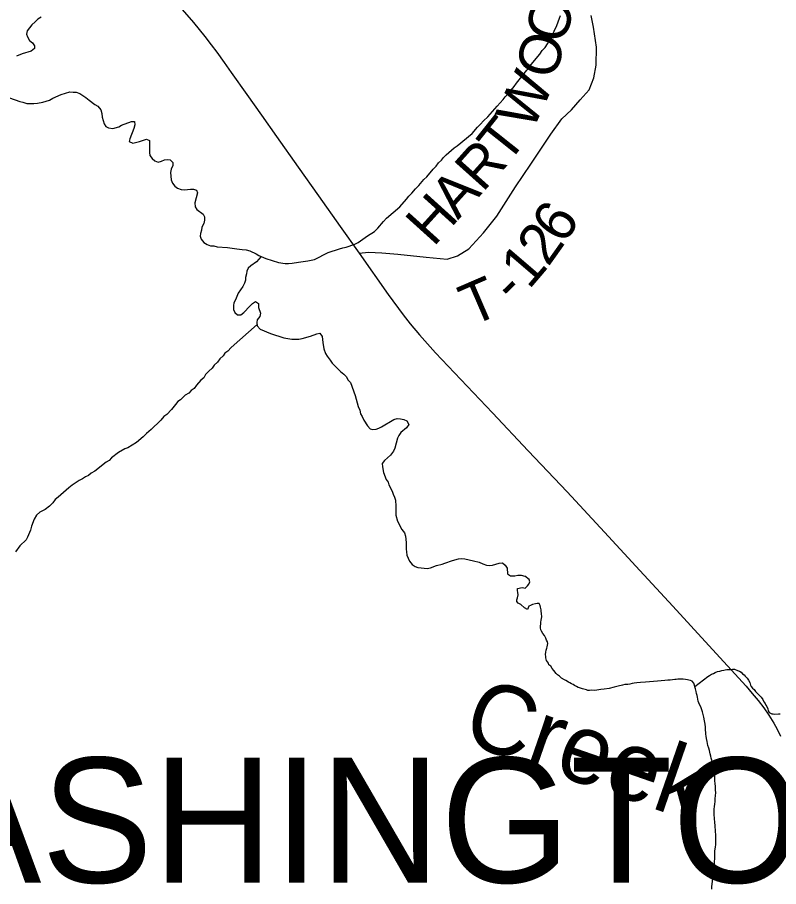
# Model space of a CAD drawing. Extents: x -14196 to 143, y -6096 to 28.
# Drawn here: x 62.594 to 63.633, y 20.504 to 21.69 of the extents above; entities that cross this region are included whole.
import ezdxf

# ---------------------------------------------------------------- set-up
doc = ezdxf.new("R2010")
doc.units = 0
for name, color, linetype in [('GM_X_Minor_River', 7, 'Continuous'), ('GM_X_Minor_River_Text', 7, 'Continuous'), ('GM_X_State_Route', 7, 'Continuous'), ('GM_X_Township_Road', 7, 'Continuous'), ('GM_X_Township_Road_Text', 7, 'Continuous'), ('GM_X_Township_Text', 7, 'Continuous')]:
    doc.layers.add(name, color=color, linetype=linetype)

msp = doc.modelspace()

# ---------------------------------------------------------------- linework, layer by layer
at = {"layer": 'GM_X_Minor_River'}
for points in [[(62.6266, 21.6899), (62.622, 21.6872), (62.6182, 21.6834), (62.6137, 21.6795), (62.6073, 21.6711), (62.6066, 21.6666)], [(62.9008, 21.373), (62.9062, 21.3723), (62.9111, 21.3712), (62.9196, 21.3671), (62.9234, 21.3648), (62.9329, 21.3608), (62.9501, 21.3552), (62.9593, 21.3538), (62.9639, 21.3538), (62.9688, 21.3543), (62.9775, 21.3559), (62.9905, 21.3575), (62.995, 21.3583), (62.9992, 21.3595), (63.0181, 21.3688), (63.0337, 21.3739), (63.0379, 21.3751), (63.0424, 21.3763), (63.0546, 21.3802), (63.0591, 21.3825), (63.0716, 21.3914), (63.0814, 21.3975), (63.0859, 21.4021), (63.0934, 21.4113), (63.0976, 21.4155), (63.1157, 21.4313), (63.1251, 21.4417), (63.1281, 21.4459), (63.1322, 21.4497), (63.1371, 21.4555), (63.142, 21.4604), (63.1488, 21.4685), (63.1529, 21.4723), (63.1612, 21.4827), (63.1654, 21.4865), (63.1687, 21.4911), (63.1725, 21.4946), (63.1755, 21.4984), (63.1793, 21.5022), (63.1898, 21.5118), (63.194, 21.5145), (63.2144, 21.5314), (63.2219, 21.5399), (63.226, 21.5437), (63.2302, 21.5483), (63.2358, 21.5537), (63.2486, 21.5686), (63.2569, 21.5775), (63.2595, 21.5813), (63.2637, 21.5855), (63.272, 21.5955), (63.275, 21.6), (63.2892, 21.6177), (63.2926, 21.6215), (63.2952, 21.6253), (63.3069, 21.6395), (63.3103, 21.6445), (63.314, 21.6483), (63.3174, 21.6533), (63.3226, 21.6632), (63.3301, 21.6785), (63.3338, 21.6884), (63.3349, 21.6922)], [(62.6066, 21.6666), (62.6078, 21.6628), (62.6105, 21.6582), (62.6144, 21.6548), (62.6171, 21.6507), (62.6171, 21.6469), (62.6129, 21.6434), (62.6004, 21.6399), (62.5928, 21.6368)], [(62.5832, 21.5797), (62.5973, 21.5749), (62.6015, 21.5738), (62.6068, 21.5723), (62.6164, 21.572), (62.6213, 21.5724), (62.6289, 21.574), (62.638, 21.5768), (62.6422, 21.5795), (62.6535, 21.5845), (62.6657, 21.5881), (62.6699, 21.5877), (62.674, 21.5874), (62.679, 21.5859), (62.6874, 21.5803), (62.6917, 21.5765), (62.6997, 21.5705), (62.7036, 21.5683), (62.7078, 21.5634), (62.7094, 21.5585), (62.7098, 21.5535), (62.7122, 21.5444), (62.7145, 21.5407), (62.7183, 21.5388), (62.724, 21.5381), (62.7324, 21.5401), (62.7362, 21.5424), (62.7498, 21.5475), (62.7536, 21.5475), (62.7544, 21.543), (62.753, 21.538), (62.7474, 21.5239), (62.7467, 21.5201), (62.7517, 21.5178), (62.7608, 21.5202), (62.7703, 21.5233), (62.7741, 21.5215), (62.7742, 21.5051), (62.7747, 21.501), (62.7778, 21.4972), (62.7816, 21.4938), (62.7862, 21.4923), (62.7907, 21.4935), (62.7945, 21.4951), (62.7987, 21.4955), (62.8025, 21.4952), (62.806, 21.4914), (62.806, 21.4876), (62.8038, 21.4826), (62.8027, 21.4781), (62.8036, 21.4682), (62.8055, 21.4633), (62.8086, 21.4595), (62.8124, 21.4565), (62.8174, 21.455), (62.822, 21.4543), (62.8303, 21.4551), (62.8345, 21.4552), (62.8383, 21.4541), (62.8399, 21.4503), (62.8359, 21.4366), (62.8367, 21.4313), (62.839, 21.4275), (62.8474, 21.4211), (62.8494, 21.4173), (62.8494, 21.4132), (62.8483, 21.4082), (62.8457, 21.4036), (62.845, 21.3994), (62.8439, 21.3949), (62.8436, 21.3911), (62.8447, 21.3869), (62.8486, 21.3827), (62.8528, 21.3797), (62.8574, 21.3779), (62.862, 21.3779), (62.8665, 21.3768), (62.8806, 21.3758), (62.8932, 21.3737), (62.897, 21.3733), (62.9008, 21.373)], [(62.9268, 21.3634), (62.9204, 21.3561), (62.9125, 21.3507), (62.9087, 21.3476), (62.9069, 21.3434), (62.9065, 21.3396), (62.9054, 21.335), (62.9051, 21.3312), (62.904, 21.327), (62.9014, 21.3225), (62.8954, 21.3133), (62.8917, 21.3041), (62.8894, 21.3003), (62.8887, 21.2965), (62.8891, 21.2912), (62.8907, 21.287), (62.8945, 21.284), (62.8991, 21.284), (62.9029, 21.2871), (62.9112, 21.2959), (62.9149, 21.2994), (62.9191, 21.3021), (62.9229, 21.2991), (62.923, 21.2938), (62.9257, 21.2862), (62.9246, 21.2816), (62.9213, 21.277), (62.9205, 21.2732), (62.9213, 21.2687), (62.9252, 21.2642), (62.9393, 21.2586), (62.9577, 21.2523), (62.9683, 21.2505), (62.9725, 21.2506), (62.9782, 21.2506), (62.9828, 21.2514), (62.9938, 21.2546), (63.0025, 21.2581), (63.0067, 21.2589), (63.0098, 21.2543), (63.0106, 21.246), (63.0123, 21.2373), (63.0146, 21.2312), (63.0169, 21.2274), (63.0208, 21.2221), (63.0235, 21.218), (63.035, 21.2067), (63.0396, 21.2029), (63.0431, 21.1992), (63.045, 21.1954), (63.0485, 21.1916), (63.0548, 21.1738), (63.0591, 21.1587), (63.0611, 21.1538), (63.0623, 21.1488), (63.0646, 21.145), (63.0666, 21.1401), (63.0716, 21.1326), (63.0754, 21.1284), (63.0792, 21.1273), (63.0834, 21.1281), (63.0872, 21.1293), (63.091, 21.1312), (63.1076, 21.1413), (63.1122, 21.1425), (63.1168, 21.1421), (63.1214, 21.141), (63.1252, 21.1392), (63.1283, 21.1343), (63.1249, 21.1297), (63.117, 21.1235), (63.1143, 21.1193), (63.1125, 21.1155), (63.1092, 21.1022), (63.1073, 21.098), (63.1032, 21.0926), (63.0991, 21.0888), (63.0949, 21.0853), (63.0919, 21.0811), (63.092, 21.0765), (63.0936, 21.0689), (63.0971, 21.0595), (63.0998, 21.0557), (63.101, 21.0519), (63.1056, 21.0432), (63.1068, 21.0394), (63.1087, 21.0353), (63.1099, 21.0311), (63.1104, 21.0227), (63.1105, 21.0106), (63.1125, 21.0026), (63.1187, 20.9909), (63.1222, 20.9864), (63.1238, 20.9822), (63.1246, 20.9735), (63.1243, 20.9689), (63.1247, 20.9644), (63.1251, 20.9606), (63.1252, 20.956), (63.1291, 20.9477), (63.1325, 20.9432)], [(62.921, 21.2705), (62.8855, 21.2391), (62.8813, 21.2345), (62.8772, 21.2318), (62.8749, 21.228), (62.8704, 21.2237), (62.867, 21.2191), (62.8625, 21.2153), (62.8599, 21.2111), (62.8554, 21.2072), (62.8508, 21.2023), (62.8482, 21.1981), (62.8445, 21.1946), (62.8384, 21.1881), (62.8354, 21.1835), (62.8309, 21.1808), (62.8279, 21.177), (62.823, 21.1743), (62.8166, 21.1681), (62.8128, 21.1658), (62.8098, 21.1616), (62.8041, 21.1547), (62.7977, 21.1478), (62.794, 21.1451), (62.7898, 21.1401), (62.7853, 21.1355), (62.7804, 21.1317), (62.7766, 21.1274), (62.7702, 21.1221), (62.7657, 21.1175), (62.7563, 21.1098), (62.7449, 21.1024), (62.7404, 21.1009), (62.732, 21.0962), (62.7222, 21.0889), (62.7192, 21.0851), (62.7151, 21.0828), (62.6996, 21.0705), (62.6947, 21.0678), (62.6909, 21.0647), (62.6867, 21.0631), (62.6829, 21.0604), (62.6784, 21.0581), (62.6686, 21.0515), (62.664, 21.0481), (62.6497, 21.035), (62.6455, 21.0319), (62.6422, 21.0273), (62.6376, 21.0231), (62.632, 21.0185), (62.6282, 21.0166), (62.6244, 21.0146), (62.6199, 21.0108), (62.6169, 21.0051), (62.6132, 20.9955), (62.6117, 20.9902), (62.608, 20.9807), (62.6058, 20.9768), (62.5975, 20.9688), (62.5915, 20.9604)], [(63.1325, 20.9432), (63.1367, 20.9405), (63.1406, 20.9394), (63.1448, 20.9387), (63.1531, 20.938), (63.1577, 20.9388), (63.166, 20.942), (63.1736, 20.9439), (63.1774, 20.9451), (63.1877, 20.9486), (63.196, 20.951), (63.2002, 20.9514), (63.2044, 20.9511), (63.2166, 20.9482), (63.2242, 20.9467), (63.2292, 20.9441), (63.2342, 20.9426), (63.2384, 20.9419), (63.2422, 20.9423), (63.2513, 20.9451), (63.2558, 20.9455), (63.2597, 20.9425), (63.2624, 20.9383), (63.2628, 20.9307), (63.2667, 20.928), (63.2726, 20.9277), (63.2768, 20.9287), (63.2815, 20.9287), (63.2864, 20.9276)], [(63.3725, 20.7717), (63.3706, 20.7725), (63.3652, 20.7739), (63.361, 20.775), (63.3591, 20.7758), (63.3568, 20.7769), (63.3542, 20.7784), (63.3522, 20.7795), (63.3499, 20.7806), (63.348, 20.7821), (63.3461, 20.7828), (63.3423, 20.7851), (63.3404, 20.7862), (63.3366, 20.7881), (63.3339, 20.7911), (63.3312, 20.7929), (63.3293, 20.7948), (63.3258, 20.7986), (63.3239, 20.8016), (63.3219, 20.8046), (63.3193, 20.8065), (63.3185, 20.8088), (63.3161, 20.8125), (63.3153, 20.816), (63.3149, 20.8179), (63.3145, 20.8205), (63.3149, 20.8239), (63.3156, 20.8266), (63.3163, 20.8293), (63.3171, 20.8312), (63.3174, 20.8335), (63.3178, 20.8354), (63.3174, 20.838), (63.3162, 20.8403), (63.315, 20.8429), (63.3131, 20.8463), (63.3111, 20.8494), (63.3092, 20.8524), (63.3084, 20.8543), (63.3076, 20.8569), (63.308, 20.8592), (63.3083, 20.8626), (63.3083, 20.8645), (63.3087, 20.8676), (63.309, 20.8695), (63.3097, 20.8718), (63.3093, 20.8767), (63.3089, 20.8797), (63.3085, 20.8816), (63.3077, 20.885), (63.3073, 20.8873), (63.3061, 20.89), (63.3034, 20.8903), (63.3008, 20.8899), (63.297, 20.8887), (63.294, 20.8876), (63.2921, 20.8864), (63.291, 20.8841), (63.2899, 20.8822), (63.286, 20.8844), (63.2811, 20.8886), (63.2772, 20.8908), (63.2757, 20.8931), (63.2757, 20.8953), (63.2764, 20.898), (63.2771, 20.9018), (63.2767, 20.9052), (63.2763, 20.9079), (63.2762, 20.9106), (63.2827, 20.9118), (63.285, 20.9114), (63.2869, 20.911), (63.2899, 20.9141), (63.2921, 20.9164), (63.2932, 20.9199), (63.2924, 20.9229), (63.2864, 20.9276)], [(63.5185, 20.7771), (63.536, 20.7906), (63.5382, 20.7921), (63.5412, 20.7937), (63.5439, 20.7948), (63.5461, 20.796), (63.5495, 20.7972), (63.5526, 20.798), (63.5552, 20.7988), (63.5579, 20.7992), (63.5598, 20.7996), (63.562, 20.8), (63.5647, 20.8), (63.567, 20.8), (63.57, 20.8004), (63.5723, 20.8005), (63.5765, 20.799), (63.5795, 20.7979), (63.5815, 20.7964), (63.5834, 20.7941), (63.5857, 20.793), (63.5872, 20.7911), (63.5899, 20.7881), (63.5918, 20.7855), (63.5934, 20.7824), (63.5942, 20.779), (63.5954, 20.7768), (63.5969, 20.7749), (63.5992, 20.773), (63.6011, 20.77), (63.6031, 20.7685), (63.6058, 20.7655), (63.6088, 20.7625), (63.6112, 20.7594), (63.6127, 20.756), (63.6143, 20.7538), (63.6154, 20.7515), (63.6166, 20.7496), (63.6178, 20.7466), (63.6186, 20.7439), (63.6197, 20.7417), (63.6216, 20.7406), (63.6235, 20.7398), (63.6254, 20.7395), (63.6273, 20.7391), (63.6327, 20.7395), (63.6349, 20.7396)], [(63.5469, 20.5722), (63.5469, 20.5752), (63.5468, 20.5786), (63.546, 20.5877), (63.5459, 20.5911), (63.5455, 20.593), (63.5451, 20.5957), (63.5451, 20.5984), (63.545, 20.601), (63.545, 20.6041), (63.545, 20.6071), (63.5449, 20.6098), (63.5453, 20.6132), (63.5456, 20.6166), (63.546, 20.62), (63.5463, 20.6238), (63.5466, 20.6284), (63.547, 20.6318), (63.5465, 20.636), (63.5465, 20.6406), (63.546, 20.6447), (63.5456, 20.6485), (63.5456, 20.6527), (63.5455, 20.6558), (63.5451, 20.658), (63.5447, 20.6611), (63.5443, 20.6637), (63.5435, 20.6664), (63.5431, 20.6694), (63.5423, 20.6728), (63.5415, 20.6766), (63.5407, 20.6793), (63.5403, 20.6819), (63.5391, 20.6849), (63.5383, 20.6895), (63.5375, 20.6929), (63.5363, 20.6967), (63.5351, 20.702), (63.5343, 20.7062), (63.5339, 20.7092), (63.5335, 20.7119), (63.5334, 20.7141), (63.533, 20.7176), (63.533, 20.7214), (63.5325, 20.7255), (63.5317, 20.7301), (63.5305, 20.735), (63.5297, 20.7388), (63.5289, 20.7426), (63.5278, 20.7453), (63.527, 20.7479), (63.5238, 20.7547), (63.5231, 20.757), (63.5223, 20.7596), (63.5219, 20.7623), (63.5214, 20.7646), (63.5207, 20.7672), (63.5202, 20.7703), (63.5198, 20.7721), (63.5191, 20.774), (63.5186, 20.7767), (63.5179, 20.7786), (63.5171, 20.7816), (63.5148, 20.7843), (63.5125, 20.785), (63.5102, 20.7857), (63.5083, 20.7861), (63.5056, 20.7864), (63.5026, 20.7868), (63.5007, 20.7868), (63.4972, 20.7871), (63.4954, 20.7871), (63.4931, 20.7867), (63.4912, 20.7867), (63.4878, 20.7862), (63.4847, 20.7858), (63.4817, 20.7854), (63.4775, 20.785), (63.4726, 20.7846), (63.4673, 20.7841), (63.451, 20.7828), (63.4441, 20.7824), (63.4392, 20.7819), (63.4358, 20.7815), (63.4327, 20.7811), (63.4297, 20.7803), (63.4271, 20.7799), (63.4252, 20.7795), (63.4229, 20.7795), (63.4199, 20.7787), (63.4138, 20.7775), (63.4081, 20.7759), (63.4013, 20.7743), (63.3949, 20.7735), (63.3903, 20.7727), (63.3873, 20.7723), (63.3846, 20.7718), (63.3812, 20.7714), (63.3774, 20.7718), (63.3747, 20.7717), (63.3725, 20.7717)], [(63.5417, 20.5007), (63.5416, 20.5041), (63.542, 20.5075), (63.5423, 20.5113), (63.5427, 20.5147), (63.543, 20.5174), (63.5434, 20.5204), (63.5437, 20.5223), (63.5444, 20.5258), (63.5448, 20.528), (63.5451, 20.5303), (63.5451, 20.533), (63.5454, 20.5364), (63.5454, 20.5387), (63.5458, 20.5414), (63.5457, 20.5436), (63.5457, 20.5474), (63.5457, 20.5501), (63.5456, 20.5528), (63.546, 20.555), (63.5467, 20.5585), (63.547, 20.5611), (63.547, 20.5638), (63.547, 20.5665), (63.5469, 20.5691), (63.5469, 20.5722)]]:
    msp.add_lwpolyline(points, dxfattribs=at)
at = {"layer": 'GM_X_State_Route'}
msp.add_lwpolyline([(62.8186, 21.7005), (62.8342, 21.6825), (62.8419, 21.6731), (62.8496, 21.6636), (62.8583, 21.6523), (62.8661, 21.6419), (62.8762, 21.6278), (62.8859, 21.6143), (62.9072, 21.5845), (62.9271, 21.5561), (62.9475, 21.527), (62.9772, 21.4852), (63.0048, 21.446), (63.0343, 21.4044), (63.0603, 21.3681), (63.0999, 21.3118), (63.1205, 21.2839), (63.13, 21.2718), (63.1425, 21.2566), (63.1643, 21.2322), (63.1904, 21.2048), (63.2422, 21.1501), (63.2911, 21.0986), (63.3444, 21.0425), (63.395, 20.9876), (63.4435, 20.9352), (63.4885, 20.8864), (63.5376, 20.8327), (63.5883, 20.7772), (63.5967, 20.7675), (63.6049, 20.7577), (63.6124, 20.7479), (63.6192, 20.7377), (63.626, 20.7269), (63.6306, 20.7187), (63.6353, 20.7092)], dxfattribs=at)
at = {"layer": 'GM_X_Township_Road'}
msp.add_lwpolyline([(63.0603, 21.3681), (63.0729, 21.3693), (63.0912, 21.3686), (63.1132, 21.3665), (63.1519, 21.3627), (63.1806, 21.3599), (63.1947, 21.3643), (63.2101, 21.374), (63.23, 21.3955), (63.248, 21.4185), (63.2738, 21.4584), (63.2947, 21.4895), (63.3219, 21.5301), (63.3369, 21.5512), (63.3501, 21.5635), (63.3621, 21.577), (63.3741, 21.5908), (63.3807, 21.6072), (63.3839, 21.6244), (63.384, 21.6491), (63.3802, 21.6764), (63.3769, 21.6919)], dxfattribs=at)

# ---------------------------------------------------------------- texts
at = {"layer": 'GM_X_Minor_River_Text'}
msp.add_text('Creek', height=0.0947, rotation=340.8662, dxfattribs=at).set_placement((63.1973, 20.7021))
at = {"layer": 'GM_X_Township_Road_Text'}
for s, rotation, p in [('O', 74.9283, (63.3403, 21.6517)), ('O', 75.4962, (63.3278, 21.6035)), ('W', 65.2031, (63.2965, 21.5332)), ('T', 51.5083, (63.2623, 21.4874)), ('R', 48.1599, (63.2288, 21.4498)), ('A', 47.9091, (63.1951, 21.4125)), ('H', 47.9094, (63.1616, 21.3754)), ('6', 56.4124, (63.3395, 21.3784)), ('2', 54.6159, (63.3182, 21.3483)), ('1', 49.436, (63.292, 21.3173)), ('T', 23.3837, (63.2136, 21.2677)), ('-', 43.8435, (63.271, 21.2967))]:
    msp.add_text(s, height=0.0568, rotation=rotation, dxfattribs=at).set_placement(p)
at = {"layer": 'GM_X_Township_Text'}
msp.add_text('WASHINGTON', height=0.17045, rotation=0, dxfattribs=at).set_placement((62.2596, 20.5094))

doc.saveas('drawing.dxf')
